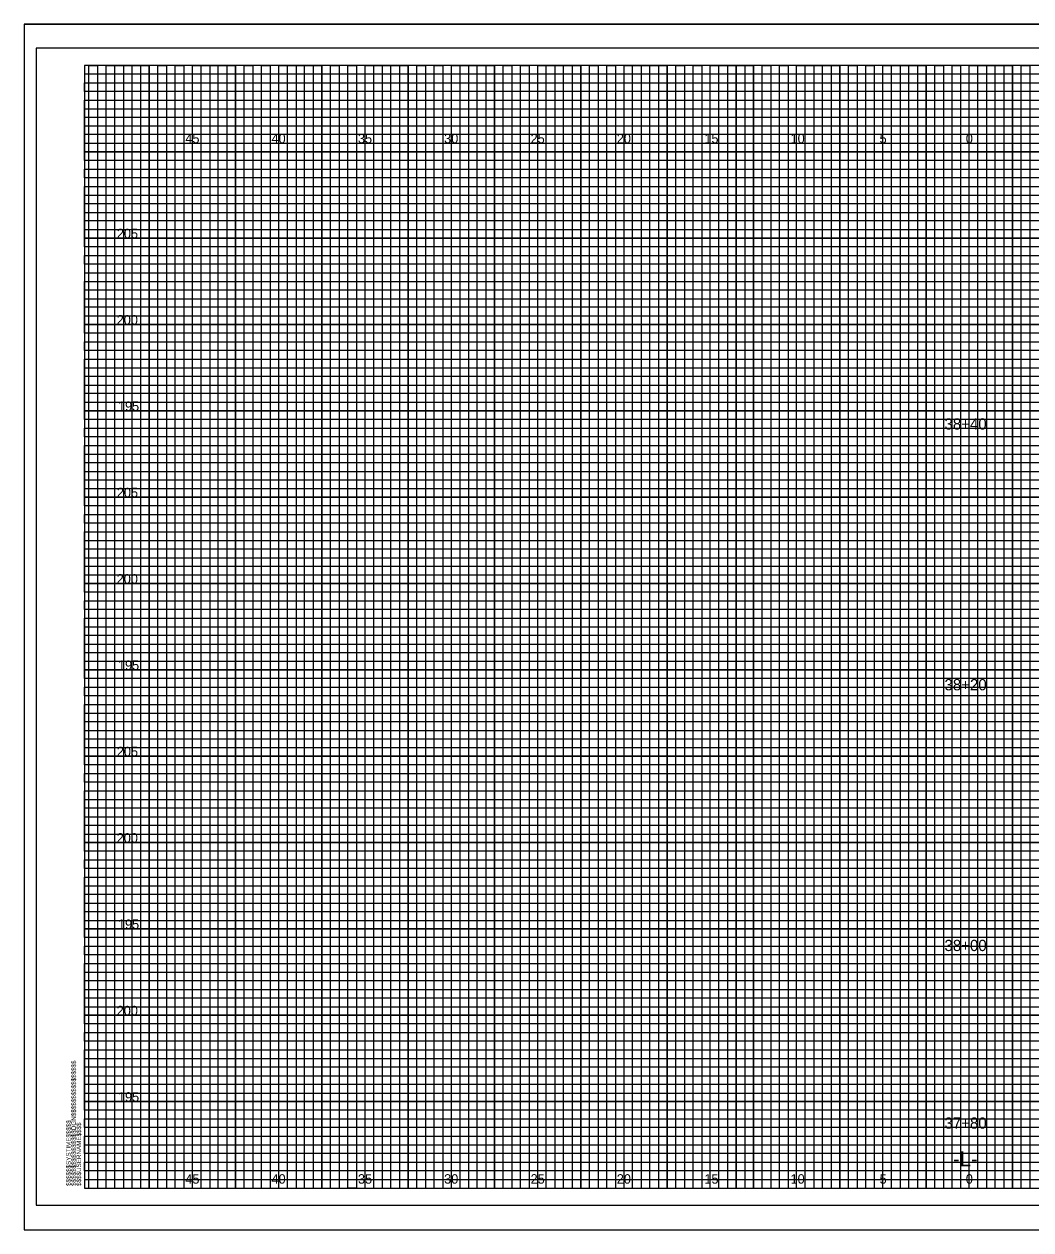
# Model space of a CAD drawing. Extents: x -4 to 103, y -2 to 6583.
# Drawn here: x -3.5 to 54.8, y 2759.8 to 2829.6 of the extents above; entities that cross this region are included whole.
import ezdxf

# ---------------------------------------------------------------- set-up
doc = ezdxf.new("R2010")
doc.units = 0
for name, color, linetype in [('Prop XS Alignment Label', 7, 'Continuous'), ('Prop XS Elevation Labels', 7, 'Continuous'), ('Prop XS Offset Labels', 7, 'Continuous'), ('Prop XS Station Labels', 7, 'Continuous'), ('Sheet Cross Section CELL', 7, 'Continuous'), ('Sheet Cross Section Grid Major CELL', 7, 'Continuous'), ('Sheet Cross Section Grid Middle CELL', 7, 'Continuous'), ('Sheet Cutting Line CELL', 7, 'Continuous'), ('Sheet DOT Grid CELL', 7, 'Continuous'), ('Sheet Plot Border Inside CELL', 7, 'Continuous'), ('Sheet Plot Border Outside CELL', 7, 'Continuous')]:
    doc.layers.add(name, color=color, linetype=linetype)

msp = doc.modelspace()

# ---------------------------------------------------------------- linework, layer by layer
at = {"layer": 'Sheet Cross Section CELL'}
msp.add_lwpolyline([(102.5, 2827.175), (0, 2827.175), (0, 2762.175), (102.5, 2762.175)], close=True, dxfattribs=at)
at = {"layer": 'Sheet Cross Section Grid Major CELL'}
for points in [[(1.25, 2762.175), (1.25, 2827.175), (3.75, 2827.175), (3.75, 2762.175), (6.25, 2762.175), (6.25, 2827.175), (8.75, 2827.175), (8.75, 2762.175), (11.25, 2762.175), (11.25, 2827.175), (13.75, 2827.175), (13.75, 2762.175), (16.25, 2762.175), (16.25, 2827.175), (18.75, 2827.175), (18.75, 2762.175), (21.25, 2762.175), (21.25, 2827.175), (23.75, 2827.175), (23.75, 2762.175), (26.25, 2762.175), (26.25, 2827.175), (28.75, 2827.175), (28.75, 2762.175), (31.25, 2762.175), (31.25, 2827.175), (33.75, 2827.175), (33.75, 2762.175), (36.25, 2762.175), (36.25, 2827.175), (38.75, 2827.175), (38.75, 2762.175), (41.25, 2762.175), (41.25, 2827.175), (43.75, 2827.175), (43.75, 2762.175), (46.25, 2762.175), (46.25, 2827.175), (48.75, 2827.175), (48.75, 2762.175), (51.25, 2762.175), (51.25, 2827.175), (53.75, 2827.175), (53.75, 2762.175)], [(102.5, 2822.175), (0, 2822.175), (0, 2824.675), (74.25, 2824.675)], [(102.5, 2817.175), (0, 2817.175), (0, 2819.675), (102.5, 2819.675)], [(102.5, 2812.175), (0, 2812.175), (0, 2814.675), (102.5, 2814.675)], [(102.5, 2807.175), (0, 2807.175), (0, 2809.675), (102.5, 2809.675)], [(102.5, 2802.175), (0, 2802.175), (0, 2804.675), (102.5, 2804.675)], [(102.5, 2797.175), (0, 2797.175), (0, 2799.675), (102.5, 2799.675)], [(102.5, 2792.175), (0, 2792.175), (0, 2794.675), (102.5, 2794.675)], [(102.5, 2787.175), (0, 2787.175), (0, 2789.675), (102.5, 2789.675)], [(102.5, 2782.175), (0, 2782.175), (0, 2784.675), (102.5, 2784.675)], [(102.5, 2777.175), (0, 2777.175), (0, 2779.675), (102.5, 2779.675)], [(102.5, 2772.175), (0, 2772.175), (0, 2774.675), (102.5, 2774.675)], [(102.5, 2767.175), (0, 2767.175), (0, 2769.675), (102.5, 2769.675)], [(0, 2764.675), (102.5, 2764.675)]]:
    msp.add_lwpolyline(points, dxfattribs=at)
at = {"layer": 'Sheet Cross Section Grid Middle CELL'}
for points in [[(0, 2824.175), (0, 2825.175), (74.25, 2825.175), (74.25, 2825.675), (0, 2825.675), (0, 2826.175), (74.25, 2826.175), (74.25, 2826.675), (0, 2826.675)], [(0.25, 2762.175), (0.25, 2827.175), (0.75, 2827.175), (0.75, 2762.175), (1.75, 2762.175), (1.75, 2827.175), (2.25, 2827.175), (2.25, 2762.175), (2.75, 2762.175), (2.75, 2827.175), (3.25, 2827.175), (3.25, 2762.175), (4.25, 2762.175), (4.25, 2827.175), (4.75, 2827.175), (4.75, 2762.175), (5.25, 2762.175), (5.25, 2827.175), (5.75, 2827.175), (5.75, 2762.175), (6.75, 2762.175), (6.75, 2827.175), (7.25, 2827.175), (7.25, 2762.175), (7.75, 2762.175), (7.75, 2827.175), (8.25, 2827.175), (8.25, 2762.175), (9.25, 2762.175), (9.25, 2827.175), (9.75, 2827.175), (9.75, 2762.175), (10.25, 2762.175), (10.25, 2827.175), (10.75, 2827.175), (10.75, 2762.175), (11.75, 2762.175), (11.75, 2827.175), (12.25, 2827.175), (12.25, 2762.175), (12.75, 2762.175), (12.75, 2827.175), (13.25, 2827.175), (13.25, 2762.175), (14.25, 2762.175), (14.25, 2827.175), (14.75, 2827.175), (14.75, 2762.175), (15.75, 2762.175), (15.25, 2762.175), (15.25, 2827.175), (15.75, 2827.175), (15.75, 2762.175), (16.75, 2762.175), (16.75, 2827.175), (17.25, 2827.175), (17.25, 2762.175), (17.75, 2762.175), (17.75, 2827.175), (18.25, 2827.175), (18.25, 2762.175), (19.25, 2762.175), (19.25, 2827.175), (19.75, 2827.175), (19.75, 2762.175), (20.25, 2762.175), (20.25, 2827.175), (20.75, 2827.175), (20.75, 2762.175), (21.75, 2762.175), (21.75, 2827.175), (22.25, 2827.175), (22.25, 2762.175), (22.75, 2762.175), (22.75, 2827.175), (23.25, 2827.175), (23.25, 2762.175), (24.25, 2762.175), (24.25, 2827.175), (24.75, 2827.175), (24.75, 2762.175), (25.25, 2762.175), (25.25, 2827.175), (25.75, 2827.175), (25.75, 2762.175), (26.75, 2762.175), (26.75, 2827.175), (27.25, 2827.175), (27.25, 2762.175), (27.75, 2762.175), (27.75, 2827.175), (28.25, 2827.175), (28.25, 2762.175), (29.25, 2762.175), (29.25, 2827.175), (29.75, 2827.175), (29.75, 2762.175), (30.25, 2762.175), (30.25, 2827.175), (30.75, 2827.175), (30.75, 2762.175)], [(30.75, 2762.175), (31.75, 2762.175), (31.75, 2827.175), (32.25, 2827.175), (32.25, 2762.175), (32.75, 2762.175), (32.75, 2827.175), (33.25, 2827.175), (33.25, 2762.175), (34.25, 2762.175), (34.25, 2827.175), (34.75, 2827.175), (34.75, 2762.175), (35.25, 2762.175), (35.25, 2827.175), (35.75, 2827.175), (35.75, 2762.175), (36.75, 2762.175), (36.75, 2827.175), (37.25, 2827.175), (37.25, 2762.175), (37.75, 2762.175), (37.75, 2827.175), (37.75, 2762.175)], [(38.25, 2827.175), (38.25, 2762.175), (39.25, 2762.175), (39.25, 2827.175), (39.75, 2827.175), (39.75, 2762.175), (40.25, 2762.175), (40.25, 2827.175), (40.75, 2827.175), (40.75, 2762.175), (41.75, 2762.175), (41.75, 2827.175), (42.25, 2827.175), (42.25, 2762.175), (42.75, 2762.175), (42.75, 2827.175), (43.25, 2827.175), (43.25, 2762.175), (43.75, 2762.175), (44.25, 2762.175), (44.25, 2827.175), (44.75, 2827.175), (44.75, 2762.175), (45.25, 2762.175), (45.25, 2827.175), (45.75, 2827.175), (45.75, 2762.175), (46.75, 2762.175), (46.75, 2827.175), (47.25, 2827.175), (47.25, 2762.175), (47.75, 2762.175), (47.75, 2827.175), (48.25, 2827.175), (48.25, 2762.175), (49.25, 2762.175), (49.25, 2827.175), (49.75, 2827.175), (49.75, 2762.175), (50.25, 2762.175), (50.25, 2827.175), (50.75, 2827.175), (50.75, 2762.175), (51.75, 2762.175), (51.75, 2827.175), (52.25, 2827.175), (52.25, 2762.175), (52.75, 2762.175), (52.75, 2827.175), (53.25, 2827.175), (53.25, 2762.175), (54.25, 2762.175), (54.25, 2827.175), (54.75, 2827.175), (54.75, 2762.175), (55.25, 2762.175)], [(102.5, 2824.175), (0, 2824.175)], [(102.5, 2823.175), (0, 2823.175), (0, 2823.675), (102.5, 2823.675)], [(102.5, 2821.675), (0, 2821.675), (0, 2822.675), (102.5, 2822.675)], [(102.5, 2820.675), (0, 2820.675), (0, 2821.175), (102.5, 2821.175)], [(102.5, 2819.175), (0, 2819.175), (0, 2820.175), (102.5, 2820.175)], [(102.5, 2818.175), (0, 2818.175), (0, 2818.675), (102.5, 2818.675)], [(102.5, 2816.675), (0, 2816.675), (0, 2817.675), (102.5, 2817.675)], [(102.5, 2815.675), (0, 2815.675), (0, 2816.175), (102.5, 2816.175)], [(0, 2815.175), (102.5, 2815.175)], [(102.5, 2814.175), (0, 2814.175)], [(102.5, 2813.175), (0, 2813.175), (0, 2813.675), (102.5, 2813.675)], [(102.5, 2811.675), (0, 2811.675), (0, 2812.675), (102.5, 2812.675)], [(102.5, 2810.675), (0, 2810.675), (0, 2811.175), (102.5, 2811.175)], [(102.5, 2809.175), (0, 2809.175), (0, 2810.175), (102.5, 2810.175)], [(102.5, 2808.175), (0, 2808.175), (0, 2808.675), (102.5, 2808.675)], [(102.5, 2806.675), (0, 2806.675), (0, 2807.675), (102.5, 2807.675)], [(102.5, 2805.675), (0, 2805.675), (0, 2806.175), (102.5, 2806.175)], [(102.5, 2804.175), (0, 2804.175), (0, 2805.175), (102.5, 2805.175)], [(102.5, 2803.175), (0, 2803.175), (0, 2803.675), (102.5, 2803.675)], [(102.5, 2801.675), (0, 2801.675), (0, 2802.675), (102.5, 2802.675)], [(102.5, 2800.675), (0, 2800.675), (0, 2801.175), (102.5, 2801.175)], [(102.5, 2799.175), (0, 2799.175), (0, 2800.175), (102.5, 2800.175)], [(102.5, 2798.175), (0, 2798.175), (0, 2798.675), (102.5, 2798.675)], [(102.5, 2796.675), (0, 2796.675), (0, 2797.675), (102.5, 2797.675)], [(102.5, 2795.675), (0, 2795.675), (0, 2796.175), (102.5, 2796.175)], [(102.5, 2794.175), (0, 2794.175), (0, 2795.175), (102.5, 2795.175)], [(102.5, 2793.175), (0, 2793.175), (0, 2793.675)], [(0, 2793.675), (102.5, 2793.675)], [(102.5, 2791.675), (0, 2791.675), (0, 2792.675), (102.5, 2792.675)], [(102.5, 2790.675), (0, 2790.675), (0, 2791.175), (102.5, 2791.175)], [(102.5, 2789.175), (0, 2789.175), (0, 2790.175), (102.5, 2790.175)], [(102.5, 2788.175), (0, 2788.175), (0, 2788.675), (102.5, 2788.675)], [(102.5, 2786.675), (0, 2786.675), (0, 2787.675), (102.5, 2787.675)], [(102.5, 2785.675), (0, 2785.675), (0, 2786.175), (102.5, 2786.175)], [(102.5, 2784.175), (0, 2784.175), (0, 2785.175), (102.5, 2785.175)], [(102.5, 2783.175), (0, 2783.175), (0, 2783.675), (102.5, 2783.675)], [(102.5, 2781.675), (0, 2781.675), (0, 2782.675), (102.5, 2782.675)], [(102.5, 2780.675), (0, 2780.675), (0, 2781.175), (102.5, 2781.175)], [(102.5, 2779.175), (0, 2779.175), (0, 2780.175), (102.5, 2780.175)], [(102.5, 2778.175), (0, 2778.175), (0, 2778.675), (102.5, 2778.675)], [(102.5, 2776.675), (0, 2776.675), (0, 2777.675), (102.5, 2777.675)], [(102.5, 2775.675), (0, 2775.675), (0, 2776.175), (102.5, 2776.175)], [(102.5, 2774.175), (0, 2774.175), (0, 2775.175), (102.5, 2775.175)], [(102.5, 2773.175), (0, 2773.175), (0, 2773.675), (102.5, 2773.675)], [(102.5, 2771.675), (0, 2771.675), (0, 2772.675), (102.5, 2772.675)], [(102.5, 2770.675), (0, 2770.675), (0, 2771.175), (102.5, 2771.175)], [(102.5, 2769.175), (0, 2769.175), (0, 2770.175), (102.5, 2770.175)], [(102.5, 2768.175), (0, 2768.175), (0, 2768.675), (102.5, 2768.675)], [(102.5, 2766.675), (0, 2766.675), (0, 2767.675), (102.5, 2767.675)], [(102.5, 2765.675), (0, 2765.675), (0, 2766.175), (102.5, 2766.175)], [(102.5, 2764.175), (0, 2764.175), (0, 2765.175), (102.5, 2765.175)], [(102.5, 2763.175), (0, 2763.175), (0, 2763.675), (102.5, 2763.675)], [(0, 2762.675), (102.5, 2762.675)]]:
    msp.add_lwpolyline(points, dxfattribs=at)
at = {"layer": 'Sheet Cutting Line CELL'}
for p, q in [((-3.5, 2829.575), (103.4, 2829.575)), ((-3.5, 2829.575), (-3.5, 2759.75)), ((-3.5, 2759.75), (103.4, 2759.75))]:
    msp.add_line(p, q, dxfattribs=at)
at = {"layer": 'Sheet DOT Grid CELL'}
for p, q in [((1.25, 2762.175), (1.25, 2827.175)), ((3.75, 2762.175), (3.75, 2827.175)), ((6.25, 2762.175), (6.25, 2827.175)), ((8.75, 2762.175), (8.75, 2827.175)), ((11.25, 2762.175), (11.25, 2827.175)), ((13.75, 2762.175), (13.75, 2827.175)), ((16.25, 2762.175), (16.25, 2827.175)), ((18.75, 2762.175), (18.75, 2827.175)), ((21.25, 2762.175), (21.25, 2827.175)), ((23.75, 2762.175), (23.75, 2827.175)), ((26.25, 2762.175), (26.25, 2827.175)), ((28.75, 2762.175), (28.75, 2827.175)), ((31.25, 2762.175), (31.25, 2827.175)), ((33.75, 2762.175), (33.75, 2827.175)), ((36.25, 2762.175), (36.25, 2827.175)), ((38.75, 2762.175), (38.75, 2827.175)), ((41.25, 2762.175), (41.25, 2827.175)), ((43.75, 2762.175), (43.75, 2827.175)), ((46.25, 2762.175), (46.25, 2827.175)), ((48.75, 2762.175), (48.75, 2827.175)), ((51.25, 2762.175), (51.25, 2827.175)), ((53.75, 2762.175), (53.75, 2827.175)), ((0, 2824.675), (74.25, 2824.675)), ((0, 2822.175), (102.5, 2822.175)), ((0, 2819.675), (102.5, 2819.675)), ((0, 2817.175), (102.5, 2817.175)), ((0, 2814.675), (102.5, 2814.675)), ((0, 2812.175), (102.5, 2812.175)), ((0, 2809.675), (102.5, 2809.675)), ((0, 2807.175), (102.5, 2807.175)), ((0, 2804.675), (102.5, 2804.675)), ((0, 2802.175), (102.5, 2802.175)), ((0, 2799.675), (102.5, 2799.675)), ((0, 2797.175), (102.5, 2797.175)), ((0, 2794.675), (102.5, 2794.675)), ((0, 2792.175), (102.5, 2792.175)), ((0, 2789.675), (102.5, 2789.675)), ((0, 2787.175), (102.5, 2787.175)), ((0, 2784.675), (102.5, 2784.675)), ((0, 2782.175), (102.5, 2782.175)), ((0, 2779.675), (102.5, 2779.675)), ((0, 2777.175), (102.5, 2777.175)), ((0, 2774.675), (102.5, 2774.675)), ((0, 2772.175), (102.5, 2772.175)), ((0, 2769.675), (102.5, 2769.675)), ((0, 2767.175), (102.5, 2767.175)), ((0, 2764.675), (102.5, 2764.675))]:
    msp.add_line(p, q, dxfattribs=at)
at = {"layer": 'Sheet Plot Border Inside CELL'}
msp.add_lwpolyline([(103, 2828.175), (-2.8, 2828.175), (-2.8, 2761.175), (103, 2761.175)], close=True, dxfattribs=at)
at = {"layer": 'Sheet Plot Border Outside CELL'}
msp.add_lwpolyline([(103.4, 2829.575), (-3.5, 2829.575), (-3.5, 2759.75), (103.4, 2759.75)], close=True, dxfattribs=at)

# ---------------------------------------------------------------- texts
at = {"layer": 'Prop XS Alignment Label'}
msp.add_text('-L-', height=0.875, dxfattribs=at).set_placement((50.307, 2763.425))
at = {"layer": 'Prop XS Elevation Labels'}
for s, p in [('205', (1.872, 2817.175)), ('200', (1.864, 2812.175)), ('195', (1.938, 2807.175)), ('205', (1.872, 2802.175)), ('200', (1.864, 2797.175)), ('195', (1.938, 2792.175)), ('205', (1.872, 2787.175)), ('200', (1.864, 2782.175)), ('195', (1.938, 2777.175)), ('200', (1.864, 2772.175)), ('195', (1.938, 2767.175))]:
    msp.add_text(s, height=0.55, dxfattribs=at).set_placement(p)
at = {"layer": 'Prop XS Offset Labels'}
for s, p in [('45', (5.84, 2822.675)), ('40', (10.831, 2822.675)), ('35', (15.84, 2822.675)), ('30', (20.831, 2822.675)), ('25', (25.84, 2822.675)), ('20', (30.831, 2822.675)), ('15', (35.906, 2822.675)), ('10', (40.897, 2822.675)), ('5', (46.057, 2822.675)), ('0', (51.049, 2822.675)), ('0', (51.049, 2822.675)), ('40', (10.831, 2762.425)), ('35', (15.84, 2762.425)), ('30', (20.831, 2762.425)), ('25', (25.84, 2762.425)), ('20', (30.831, 2762.425)), ('10', (40.897, 2762.425)), ('0', (51.049, 2762.425)), ('0', (51.049, 2762.425)), ('45', (5.84, 2762.425)), ('15', (35.906, 2762.425)), ('5', (46.057, 2762.425))]:
    msp.add_text(s, height=0.55, dxfattribs=at).set_placement(p)
at = {"layer": 'Prop XS Station Labels'}
for s, p in [('38+40', (49.816, 2806.097)), ('38+20', (49.816, 2790.997)), ('38+00', (49.816, 2775.897)), ('37+80', (49.816, 2765.611))]:
    msp.add_text(s, height=0.65, dxfattribs=at).set_placement(p)
at = {"layer": 'Sheet Cross Section CELL'}
for s, p in [('$$$$$$$$$$$$$$$$DGN$$$$$$$$$$$$$$$$', (-0.5, 2762.3)), ('$$$$$$SYSTIME$$$$$', (-0.797, 2762.3)), ('$$$$USERNAME$$$$', (-0.2, 2762.3))]:
    msp.add_text(s, height=0.2625, rotation=90, dxfattribs=at).set_placement(p)
at = {"layer": 'Sheet Cross Section Grid Major CELL'}
msp.add_text('040397', height=0.0025, rotation=90, dxfattribs=at).set_placement((-0.001, 2827.161))

doc.saveas('drawing.dxf')
